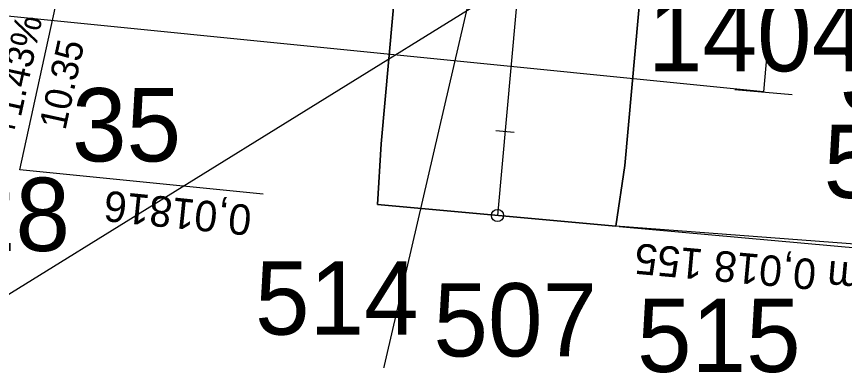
# Model space of a CAD drawing. Extents: x -748344 to -743169, y -1131966 to -1127091.
# Drawn here: x -747602.85 to -747589.31, y -1131717.22 to -1131711.59 of the extents above; entities that cross this region are included whole.
import ezdxf

# ---------------------------------------------------------------- set-up
doc = ezdxf.new("R2010")
doc.units = 0
for name, color, linetype in [('_Zabezpečovací zařízení', 7, 'Continuous'), ('_Zabezpečovací zařízení_trasa', 7, 'Continuous'), ('bublina_fialová_čára_tenká', 7, 'Continuous'), ('C3D_Trasa-Popisy trasy', 7, 'Continuous'), ('KOMUNIKACE_UPRAVA', 7, 'Continuous'), ('křížek', 7, 'Continuous'), ('křížky', 7, 'Continuous'), ('Nový stav', 7, 'Continuous'), ('OSA_KOMUNIKACE', 7, 'Continuous'), ('POP_OBLOUKY', 7, 'Continuous'), ('SKLONOVNIKY', 7, 'Continuous'), ('TRATIVOD', 7, 'Continuous'), ('Vrstva 60', 7, 'Continuous')]:
    doc.layers.add(name, color=color, linetype=linetype)

# ---------------------------------------------------------------- blocks, each defined once
blk = doc.blocks.new('POINT_DISPLAY')
blk.add_line((0, 0), (0, 0))
blk = doc.blocks.new('AeccTickCircle')
blk.add_circle((0, 0), 0.5)

msp = doc.modelspace()

# ---------------------------------------------------------------- linework, layer by layer
at = {"layer": '_Zabezpečovací zařízení'}
for p, q in [((-747590.425, -1131710.474), (-747590.628, -1131712.828)), ((-747591.099, -1131712.787), (-747590.158, -1131712.869))]:
    msp.add_line(p, q, dxfattribs=at)
at = {"layer": '_Zabezpečovací zařízení_trasa'}
msp.add_line((-747590.628, -1131712.828), (-747604.902, -1131711.398), dxfattribs=at)
at = {"layer": 'bublina_fialová_čára_tenká'}
for p, q in [((-747611.38, -1131780.164), (-747594.166, -1131705.802)), ((-747545.254, -1131718.632), (-747593.043, -1131715.025))]:
    msp.add_line(p, q, dxfattribs=at)
at = {"layer": 'C3D_Trasa-Popisy trasy'}
for p, q in [((-747595.007, -1131713.457), (-747594.708, -1131713.484)), ((-747595.131, -1131714.837), (-747594.832, -1131714.864))]:
    msp.add_line(p, q, dxfattribs=at)
at = {"layer": 'KOMUNIKACE_UPRAVA'}
for points in [[(-747592.446, -1131708.996), (-747596.376, -1131708.045), (-747596.884, -1131713.675), (-747596.943, -1131714.673), (-747593.043, -1131715.025), (-747592.9, -1131714.034), (-747592.446, -1131708.996)], [(-747596.376, -1131708.045), (-747596.884, -1131713.675), (-747596.376, -1131708.045), (-747592.446, -1131708.996), (-747592.9, -1131714.034), (-747593.043, -1131715.025), (-747596.943, -1131714.673), (-747596.884, -1131713.675)]]:
    msp.add_lwpolyline(points, dxfattribs=at)
at = {"layer": 'Nový stav'}
msp.add_line((-747589.393, -1131707.724), (-747611.929, -1131721.686), dxfattribs=at)
at = {"layer": 'OSA_KOMUNIKACE'}
msp.add_lwpolyline([(-747593.352, -1131696.768), (-747594.982, -1131714.85)], dxfattribs=at)
at = {"layer": 'POP_OBLOUKY'}
msp.add_line((-747592.99, -1131715.03), (-747587.076, -1131715.563), dxfattribs=at)
at = {"layer": 'SKLONOVNIKY'}
for p, q in [((-747602.797, -1131714.101), (-747602.157, -1131711.17)), ((-747598.817, -1131714.503), (-747602.797, -1131714.101))]:
    msp.add_line(p, q, dxfattribs=at)
at = {"layer": 'TRATIVOD'}
msp.add_line((-747592.492, -1131709.511), (-747592.707, -1131711.896), dxfattribs=at)
at = {"layer": 'Vrstva 60'}
for p, q in [((-747597.765, -1131712.113), (-747597.765, -1131712.113)), ((-747590.628, -1131712.828), (-747590.628, -1131712.828)), ((-747594.857, -1131713.471), (-747594.857, -1131713.471)), ((-747596.943, -1131714.673), (-747596.943, -1131714.673)), ((-747594.982, -1131714.85), (-747594.982, -1131714.85)), ((-747593.043, -1131715.025), (-747593.043, -1131715.025))]:
    msp.add_line(p, q, dxfattribs=at)

# ---------------------------------------------------------------- block references
at = {"layer": 'křížek', "xscale": 10, "yscale": 10, "rotation": 61.14491455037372}
for p in [(-747594.857, -1131713.471), (-747596.943, -1131714.673), (-747594.982, -1131714.85), (-747593.043, -1131715.025)]:
    msp.add_blockref('POINT_DISPLAY', p, dxfattribs=at)
at = {"layer": 'křížky', "xscale": 10, "yscale": 10, "rotation": 61.14491455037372}
for p in [(-747597.765, -1131712.113), (-747590.628, -1131712.828)]:
    msp.add_blockref('POINT_DISPLAY', p, dxfattribs=at)
at = {"layer": 'POP_OBLOUKY', "xscale": 0.19999999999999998, "yscale": 0.2, "rotation": -95.14959431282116}
msp.add_blockref('AeccTickCircle', (-747594.982, -1131714.85), dxfattribs=at)

# ---------------------------------------------------------------- texts
at = {"layer": 'POP_OBLOUKY'}
msp.add_text('KÚ km 0,018 155', height=0.5, rotation=174.8504, dxfattribs=at).set_placement((-747587.567, -1131715.769))
at = {"layer": 'SKLONOVNIKY'}
for s, height, rotation, p in [('+1.43%', 0.44, 77.6852, (-747602.856, -1131713.591)), ('10.35', 0.44, 77.6852, (-747602.053, -1131713.468)), ('0,01816', 0.5, 174.2192, (-747598.987, -1131714.686))]:
    msp.add_text(s, height=height, rotation=rotation, dxfattribs=at).set_placement(p)
at = {"layer": 'Vrstva 60'}
for s, p in [('1404', (-747592.52, -1131712.489)), ('37', (-747589.378, -1131713.139)), ('35', (-747601.944, -1131713.965)), ('506', (-747589.645, -1131714.562)), ('28', (-747603.761, -1131715.432)), ('514', (-747598.95, -1131716.802)), ('507', (-747596.03, -1131717.159)), ('515', (-747592.699, -1131717.414))]:
    msp.add_text(s, height=1.2, dxfattribs=at).set_placement(p)

doc.saveas('drawing.dxf')
